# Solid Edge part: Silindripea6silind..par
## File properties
Author: Türk
Template: iso part.par
Last saved by: Türk
Revision: 32
Application: Solid Edge
Accuracy: 0,990
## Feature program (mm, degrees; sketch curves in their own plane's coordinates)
sketch for "unnamed Hole 1" plane through (-360, 60, 0) normal (0, 1, 0) x-axis (-1, 0, 0)
hole "unnamed Hole 1" through
sketch for "unnamed Hole 2" plane through (0, 60, 0) normal (0, 1, 0) x-axis (1, 0, 0)
hole "unnamed Hole 2" through
sketch for "unnamed Hole 3" plane through (0, 99.8478, -73.8819) normal (0, 1, 0) x-axis (1, 0, 0)
hole "unnamed Hole 3" finite
sketch for "unnamed Hole 4" plane through (240, 60, 0) normal (0, 1, 0) x-axis (1, 0, 0)
hole "unnamed Hole 4" through
pattern "unnamed Pattern 1" of "unnamed Hole 2", "unnamed Hole 1", "unnamed Hole 4"
hole "unnamed Hole 5" finite
hole "unnamed Hole 6" finite
hole "unnamed Hole 7" finite
hole "unnamed Hole 8" finite
hole "unnamed Hole 9" finite
hole "unnamed Hole 10" finite
hole "unnamed Hole 11" finite
hole "unnamed Hole 12" finite
hole "unnamed Hole 13" finite
hole "unnamed Hole 14" finite
hole "unnamed Hole 15" finite
pattern "PatternOccurrence_4"  XCount = 6; YCount = 2; XOffset = 120.4 mm; YOffset = 45 mm
pattern "unnamed Pattern 2" of "unnamed Hole 3"
sketch for "unnamed Hole 16" plane through (0, 99.8478, 73.8819) normal (0, 1, 0) x-axis (1, 0, 0)
  hole centre (-301, 0.1319) bore radius 2.7295
hole "unnamed Hole 16" finite
pattern "unnamed Pattern 3" of "unnamed Hole 16", "unnamed Hole 3"
pattern "unnamed Pattern 4" of "unnamed Hole 16"
pattern "PatternOccurrence_3"  YCount = 2; XOffset = 120.4 mm; YOffset = 45 mm
hole "unnamed Hole 17" finite
hole "unnamed Hole 18" finite
hole "unnamed Hole 19" finite
hole "unnamed Hole 20" finite
hole "unnamed Hole 21" finite
hole "unnamed Hole 22" finite
hole "unnamed Hole 23" finite
hole "unnamed Hole 24" finite
hole "unnamed Hole 25" finite
hole "unnamed Hole 26" finite
hole "unnamed Hole 27" finite
Other named dimensions: "Hole_1": Diameter = 12 mm; CounterBoreDiameter = 25 mm
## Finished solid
Body 1: sheet body, 4 faces, 166 edges, 154 vertices.
  Faces by surface: plane 4
  Edges by curve: line 150, circle 16
Body 2: sheet body, 2 faces, 62 edges, 60 vertices.
  Faces by surface: plane 2
  Edges by curve: line 52, circle 10
Body 3: solid body, 475 faces, 1061 edges, 576 vertices.
  Faces by surface: plane 263, cylinder 197, cone 6, swept 6, torus 3
  Edges by curve: line 580, circle 403, ellipse 42, intersection 36
Bounding box of the edges (mm; curved faces can reach further): 390.200 x 100.848 x 180.000, from (-330, -1, -90) to (60.2, 99.8478, 90).
Cylindrical faces by radius (mm): R2.7295 x16, R3 x30, R5 x54, R5.7295 x3, R7.3756 x12, R9 x12, R10 x26, R11 x12, R12 x12, R12.5 x11, R44 x3, R44.5 x3, R47.5 x3
Conical faces (half-angle, radius in mm at the cone's reference point): 85 deg R7.5 x6
Toroidal faces (ring radius, tube radius in mm): R42 r2 x3
Planar faces by outward normal: +x 33, +y 53, +z 7, -x 31, -y 28, -z 7, oblique 104
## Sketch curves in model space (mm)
line (307, 99.8478, 61.25) -> (311, 99.8478, 61.25)
line (-295, 99.8478, -62.5) -> (-295, 99.8478, 73.75)
line (0, 99.8478, 76.25) -> (0, 99.8478, 23.7828)
line (-240, 99.8478, 76.25) -> (-240, 84.8478, 76.25)
line (-228.5464, 60, 0) -> (-252.0722, 60, 0)
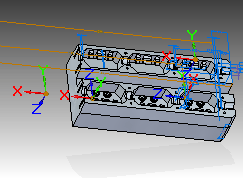
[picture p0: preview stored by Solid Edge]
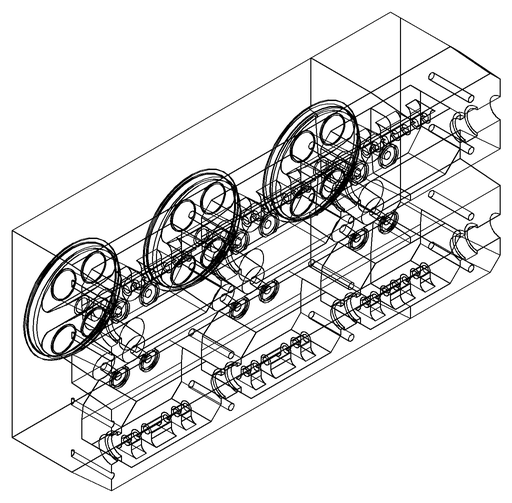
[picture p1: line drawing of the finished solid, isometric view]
